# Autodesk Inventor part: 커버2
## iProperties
Company: 한국ATC센터
Created: 2014-10
Part Number: 커버2
Document SubType Name: Modeling
Designer: KYOUNG IL JANG
Density: 1 g/cm^3
Mass: 44.7286 g
Surface Area: 161.165 cm^2
Volume: 44.7286 cm^3
Author: KYOUNG IL JANG
Revision Number: 1
